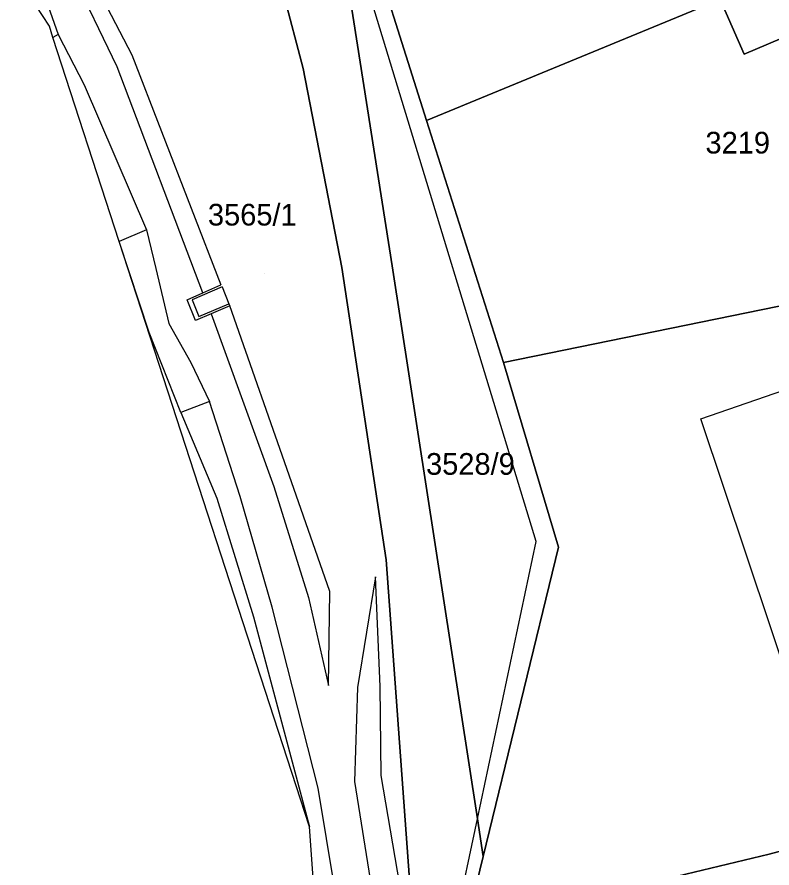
# Model space of a CAD drawing. Extents: x -262657 to -261595, y -1238015 to -1237156.
# Drawn here: x -262024.1 to -261954.5, y -1237827.1 to -1237748.7 of the extents above; entities that cross this region are included whole.
import ezdxf

# ---------------------------------------------------------------- set-up
doc = ezdxf.new("R2010")
doc.units = 0
for name, color, linetype in [('body_kn', 7, 'Continuous'), ('kladpar_druhypozemkov', 7, 'Continuous'), ('kladpar_hranice', 7, 'Continuous'), ('kladpar_parcelnecisla', 7, 'Continuous'), ('kladpar_plochy', 7, 'Continuous'), ('zappar_hrandruhpozemk', 7, 'Continuous')]:
    doc.layers.add(name, color=color, linetype=linetype)

msp = doc.modelspace()

# ---------------------------------------------------------------- linework, layer by layer
at = {"layer": 'body_kn'}
for p, q in [((-262021.16, -1237749.53), (-262021.16, -1237749.53)), ((-262020.34, -1237750.31), (-262020.34, -1237750.31)), ((-262020.83, -1237750.56), (-262020.83, -1237750.56)), ((-261957.12, -1237752.11), (-261957.12, -1237752.11)), ((-262013.57, -1237752.16), (-262013.57, -1237752.16)), ((-262014.92, -1237753.27), (-262014.92, -1237753.27)), ((-261997.77, -1237753.43), (-261997.77, -1237753.43)), ((-262017.94, -1237754.94), (-262017.94, -1237754.94)), ((-261986.41, -1237758.24), (-261986.41, -1237758.24)), ((-261986.41, -1237758.24), (-261986.41, -1237758.24)), ((-262012.21, -1237768.3), (-262012.21, -1237768.3)), ((-262014.71, -1237769.39), (-262014.71, -1237769.39)), ((-261989.56, -1237771.61), (-261989.56, -1237771.61)), ((-262011.34, -1237771.86), (-262011.34, -1237771.86)), ((-261994.21, -1237771.78), (-261994.21, -1237771.78)), ((-262005.34, -1237773.38), (-262005.34, -1237773.38)), ((-262005.24, -1237773.56), (-262005.24, -1237773.56)), ((-262008.46, -1237774.76), (-262008.46, -1237774.76)), ((-262007.98, -1237774.76), (-262007.98, -1237774.76)), ((-262007.02, -1237774.12), (-262007.02, -1237774.12)), ((-262007.02, -1237774.12), (-262007.02, -1237774.12)), ((-262004.61, -1237775.14), (-262004.61, -1237775.14)), ((-262004.61, -1237775.14), (-262004.61, -1237775.14)), ((-262004.52, -1237775.32), (-262004.52, -1237775.32)), ((-262007.37, -1237776.29), (-262007.37, -1237776.29)), ((-262006.24, -1237776.05), (-262006.24, -1237776.05)), ((-262006.24, -1237776.05), (-262006.24, -1237776.05)), ((-262010.15, -1237776.94), (-262010.15, -1237776.94)), ((-262007.69, -1237776.67), (-262007.69, -1237776.67)), ((-262011.95, -1237777.76), (-262011.95, -1237777.76)), ((-262008.13, -1237780.55), (-262008.13, -1237780.55)), ((-261979.29, -1237780.53), (-261979.29, -1237780.53)), ((-261979.29, -1237780.53), (-261979.29, -1237780.53)), ((-262006.41, -1237784.14), (-262006.41, -1237784.14)), ((-262009.03, -1237785.16), (-262009.03, -1237785.16)), ((-262009.03, -1237785.16), (-262009.03, -1237785.16)), ((-261961.11, -1237785.73), (-261961.11, -1237785.73)), ((-262000.48, -1237791.97), (-262000.48, -1237791.97)), ((-261998.83, -1237791.55), (-261998.83, -1237791.55)), ((-262003.58, -1237792.9), (-262003.58, -1237792.9)), ((-262005.73, -1237793.04), (-262005.73, -1237793.04)), ((-261976.28, -1237797.03), (-261976.28, -1237797.03)), ((-261974.24, -1237797.56), (-261974.24, -1237797.56)), ((-261990.1, -1237798.73), (-261990.1, -1237798.73)), ((-261991.11, -1237800.3), (-261991.11, -1237800.3)), ((-261997.27, -1237802.21), (-261997.27, -1237802.21)), ((-261995.31, -1237801.64), (-261995.31, -1237801.64)), ((-262000.61, -1237803.1), (-262000.61, -1237803.1)), ((-262002.35, -1237803.99), (-262002.35, -1237803.99)), ((-261995.44, -1237810.33), (-261995.44, -1237810.33)), ((-261992.75, -1237810.51), (-261992.75, -1237810.51)), ((-261990.68, -1237810.4), (-261990.68, -1237810.4)), ((-261990.57, -1237818.63), (-261990.57, -1237818.63)), ((-261993.04, -1237819.16), (-261993.04, -1237819.16)), ((-261996.38, -1237819.78), (-261996.38, -1237819.78)), ((-261981.69, -1237822.6), (-261981.69, -1237822.6)), ((-261981.69, -1237822.6), (-261981.69, -1237822.6)), ((-261997.19, -1237823.36), (-261997.19, -1237823.36)), ((-261954.82, -1237825.86), (-261954.82, -1237825.86)), ((-261981.16, -1237826.07), (-261981.16, -1237826.07)), ((-261981.16, -1237826.07), (-261981.16, -1237826.07))]:
    msp.add_line(p, q, dxfattribs=at)
at = {"layer": 'kladpar_druhypozemkov'}
for p, q in [((-261958.19, -1237759.7), (-261958.19, -1237759.7)), ((-262001.36, -1237772.3), (-262001.36, -1237772.3)), ((-261981.79, -1237788.93), (-261981.79, -1237788.93))]:
    msp.add_line(p, q, dxfattribs=at)
at = {"layer": 'kladpar_hranice'}
for points in [[(-261986.41, -1237758.24), (-261992.63, -1237738.46), (-261994.68, -1237730.89), (-261943.02, -1237721.29), (-261940.37, -1237728.85), (-261947.49, -1237731.26), (-261941.42, -1237745.41), (-261957.12, -1237752.11), (-261959.31, -1237747.04), (-261986.41, -1237758.24)], [(-261981.16, -1237826.07), (-261981.69, -1237822.6), (-261989.56, -1237771.61), (-261995.45, -1237734.05), (-261995.86, -1237731.43), (-261996.88, -1237724.96), (-261996.78, -1237724.29), (-261996.63, -1237723.32)], [(-261996.63, -1237723.32), (-261996.78, -1237724.29), (-261996.88, -1237724.96), (-261995.86, -1237731.43), (-261995.45, -1237734.05), (-261989.56, -1237771.61), (-261981.69, -1237822.6), (-261981.16, -1237826.07)], [(-261981.16, -1237826.07), (-261982.76, -1237832.64), (-261982.71, -1237834.64), (-261982.1, -1237851.16), (-261984.19, -1237867.22), (-261986.22, -1237882.06), (-261986.16, -1237883.39), (-261986.24, -1237891.44), (-261987.42, -1237876.92), (-261987.01, -1237865.75), (-261987.14, -1237847.02), (-261987.36, -1237844.03), (-261987.64, -1237832.42), (-261990.1, -1237798.73), (-261994.21, -1237771.78), (-261997.77, -1237753.43), (-262005, -1237725.87)], [(-262005, -1237725.87), (-261997.77, -1237753.43), (-261994.21, -1237771.78), (-261990.1, -1237798.73), (-261987.64, -1237832.42), (-261987.36, -1237844.03), (-261987.35, -1237844.34), (-261988.4, -1237868.65), (-261989.03, -1237883.09), (-261989.52, -1237897.17), (-261989.7, -1237902.51)], [(-261979.29, -1237780.53), (-261986.41, -1237758.24), (-261959.31, -1237747.04), (-261957.12, -1237752.11), (-261941.42, -1237745.41), (-261947.49, -1237731.26), (-261940.37, -1237728.85), (-261929.76, -1237759.16), (-261926.09, -1237769.65), (-261979.29, -1237780.53)], [(-261994.68, -1237730.89), (-261992.63, -1237738.46), (-261986.41, -1237758.24), (-261979.29, -1237780.53), (-261974.24, -1237797.56), (-261981.16, -1237826.07)], [(-261996.13, -1237922.1), (-261993.79, -1237887.01), (-261993.22, -1237878.45), (-261997.19, -1237823.36), (-262014.71, -1237769.39), (-262020.83, -1237750.56), (-262021.16, -1237749.53), (-262023.07, -1237746.54)], [(-261982.76, -1237832.64), (-261981.16, -1237826.07), (-261974.24, -1237797.56), (-261979.29, -1237780.53), (-261926.09, -1237769.65), (-261922.63, -1237778.24), (-261927.57, -1237779.48), (-261925.24, -1237804.88), (-261924.11, -1237817.62), (-261954.82, -1237825.86), (-261964.78, -1237828.28), (-261968.75, -1237829.24), (-261970.64, -1237829.7), (-261978.42, -1237831.59), (-261982.76, -1237832.64)], [(-261982.76, -1237832.64), (-261978.42, -1237831.59), (-261970.64, -1237829.7), (-261968.75, -1237829.24), (-261964.78, -1237828.28), (-261954.82, -1237825.86), (-261924.11, -1237817.62), (-261924, -1237817.96), (-261923.89, -1237818.34), (-261923.62, -1237819.21), (-261923.36, -1237820.86), (-261923.35, -1237820.94), (-261923.32, -1237821.16), (-261928.12, -1237822.84), (-261934.7, -1237824.83), (-261946.81, -1237828.25), (-261946.74, -1237828.94), (-261946.3, -1237833.58), (-261946.1, -1237835.46), (-261947.91, -1237862.67), (-261948.53, -1237879.67), (-261949.09, -1237879.78)]]:
    msp.add_lwpolyline(points, dxfattribs=at)
at = {"layer": 'kladpar_plochy'}
for points in [[(-261986.41, -1237758.24), (-261992.63, -1237738.46), (-261994.68, -1237730.89), (-261943.02, -1237721.29), (-261940.37, -1237728.85), (-261947.49, -1237731.26), (-261941.42, -1237745.41), (-261957.12, -1237752.11), (-261959.31, -1237747.04)], [(-261994.68, -1237730.89), (-261992.63, -1237738.46), (-261986.41, -1237758.24), (-261979.29, -1237780.53), (-261974.24, -1237797.56), (-261981.16, -1237826.07), (-261981.69, -1237822.6), (-261989.56, -1237771.61), (-261995.45, -1237734.05), (-261995.86, -1237731.43), (-261996.88, -1237724.96), (-261996.78, -1237724.29), (-261996.63, -1237723.32), (-261996.38, -1237724.23), (-261994.88, -1237729.86)], [(-261979.29, -1237780.53), (-261986.41, -1237758.24), (-261959.31, -1237747.04), (-261957.12, -1237752.11), (-261941.42, -1237745.41), (-261947.49, -1237731.26), (-261940.37, -1237728.85), (-261929.76, -1237759.16), (-261926.09, -1237769.65)], [(-261982.76, -1237832.64), (-261981.16, -1237826.07), (-261974.24, -1237797.56), (-261979.29, -1237780.53), (-261926.09, -1237769.65), (-261922.63, -1237778.24), (-261927.57, -1237779.48), (-261925.24, -1237804.88), (-261924.11, -1237817.62), (-261954.82, -1237825.86), (-261964.78, -1237828.28), (-261968.75, -1237829.24), (-261970.64, -1237829.7), (-261978.42, -1237831.59)]]:
    msp.add_lwpolyline(points, close=True, dxfattribs=at)
for points in [[(-261995.45, -1237734.05), (-261989.56, -1237771.61), (-261981.69, -1237822.6), (-261981.16, -1237826.07), (-261982.76, -1237832.64), (-261982.71, -1237834.64), (-261982.1, -1237851.16), (-261984.19, -1237867.22), (-261986.22, -1237882.06), (-261986.16, -1237883.39), (-261986.24, -1237891.44), (-261987.42, -1237876.92), (-261987.01, -1237865.75), (-261987.14, -1237847.02), (-261987.36, -1237844.03), (-261987.64, -1237832.42), (-261990.1, -1237798.73), (-261994.21, -1237771.78), (-261997.77, -1237753.43), (-262005, -1237725.87)], [(-262005, -1237725.87), (-261997.77, -1237753.43), (-261994.21, -1237771.78), (-261990.1, -1237798.73), (-261987.64, -1237832.42), (-261987.36, -1237844.03), (-261987.35, -1237844.34), (-261988.4, -1237868.65), (-261989.03, -1237883.09), (-261989.52, -1237897.17), (-261989.7, -1237902.51)], [(-261996.13, -1237922.1), (-261993.79, -1237887.01), (-261993.22, -1237878.45), (-261997.19, -1237823.36), (-262014.71, -1237769.39), (-262020.83, -1237750.56), (-262021.16, -1237749.53), (-262023.07, -1237746.54)], [(-261952.65, -1237848.3), (-261955.42, -1237848.55), (-261955.56, -1237848.56), (-261956.45, -1237848.64), (-261956.78, -1237843.42), (-261956.85, -1237840.34), (-261956.87, -1237839.7), (-261957.84, -1237832.53), (-261957.94, -1237831.83), (-261959.24, -1237831.99), (-261966.06, -1237832.82), (-261970.15, -1237833.27), (-261975.67, -1237833.87), (-261978.01, -1237834.13), (-261982.71, -1237834.64), (-261982.76, -1237832.64), (-261978.42, -1237831.59), (-261970.64, -1237829.7), (-261968.75, -1237829.24), (-261964.78, -1237828.28), (-261954.82, -1237825.86), (-261924.11, -1237817.62)]]:
    msp.add_lwpolyline(points, dxfattribs=at)
at = {"layer": 'zappar_hrandruhpozemk'}
for p, q in [((-261976.28, -1237797.03), (-261995.45, -1237734.05)), ((-262021.46, -1237747.17), (-262020.34, -1237750.31)), ((-262020.34, -1237750.31), (-262020.83, -1237750.56)), ((-262020.34, -1237750.31), (-262017.94, -1237754.94)), ((-262013.57, -1237752.16), (-262005.34, -1237773.38)), ((-262007.02, -1237774.12), (-262014.92, -1237753.27)), ((-262017.94, -1237754.94), (-262012.21, -1237768.3)), ((-262012.21, -1237768.3), (-262014.71, -1237769.39)), ((-262012.21, -1237768.3), (-262011.34, -1237771.86)), ((-262011.34, -1237771.86), (-262010.15, -1237776.94)), ((-262005.24, -1237773.56), (-262004.61, -1237775.14)), ((-262007.69, -1237776.67), (-262008.46, -1237774.76)), ((-262006.24, -1237776.05), (-262000.48, -1237791.97)), ((-262003.58, -1237792.9), (-262006.41, -1237784.14)), ((-261981.69, -1237822.6), (-261976.28, -1237797.03)), ((-262002.35, -1237803.99), (-261997.19, -1237823.36)), ((-261993.04, -1237819.16), (-261990.83, -1237832.9))]:
    msp.add_line(p, q, dxfattribs=at)
for points in [[(-262014.92, -1237753.27), (-262019.11, -1237744.53), (-262021.95, -1237737.13), (-262024.14, -1237733.48)], [(-262021.95, -1237737.13), (-262017.75, -1237744.12), (-262013.57, -1237752.16)], [(-262010.15, -1237776.94), (-262008.13, -1237780.55), (-262006.41, -1237784.14), (-262009.03, -1237785.16), (-262011.95, -1237777.76), (-262014.71, -1237769.39)], [(-262008.46, -1237774.76), (-262007.02, -1237774.12), (-262005.34, -1237773.38)], [(-262005.24, -1237773.56), (-262007.98, -1237774.76), (-262007.37, -1237776.29), (-262004.61, -1237775.14)], [(-262004.61, -1237775.14), (-262004.52, -1237775.32), (-262006.24, -1237776.05), (-262007.69, -1237776.67)], [(-262000.48, -1237791.97), (-261997.27, -1237802.21), (-261995.44, -1237810.33), (-261995.31, -1237801.64), (-261998.83, -1237791.55), (-262004.52, -1237775.32)], [(-261943.69, -1237800.87), (-261941.26, -1237800.04), (-261934.09, -1237797.71), (-261931.84, -1237804.29), (-261952.57, -1237811.24), (-261961.11, -1237785.73), (-261940.72, -1237778.7)], [(-262009.03, -1237785.16), (-262005.73, -1237793.04), (-262002.35, -1237803.99)], [(-261991.55, -1237876.99), (-261991.71, -1237866.06), (-261992.61, -1237846.99), (-261994.12, -1237833.53), (-261996.38, -1237819.78), (-262000.61, -1237803.1), (-262003.58, -1237792.9)], [(-261987.35, -1237844.34), (-261988.2, -1237832.48), (-261990.57, -1237818.63), (-261990.68, -1237810.4), (-261991.11, -1237800.3), (-261992.75, -1237810.51), (-261993.04, -1237819.16)], [(-261983.66, -1237850.99), (-261983.3, -1237846.2), (-261983.69, -1237832.03), (-261981.69, -1237822.6)]]:
    msp.add_lwpolyline(points, dxfattribs=at)

# ---------------------------------------------------------------- texts
at = {"layer": 'kladpar_parcelnecisla'}
for s, p in [('3219', (-261960.68, -1237761.27)), ('3565/1', (-262006.543, -1237767.91)), ('3528/9', (-261986.436, -1237790.89))]:
    msp.add_text(s, height=2, dxfattribs=at).set_placement(p)

doc.saveas('drawing.dxf')
